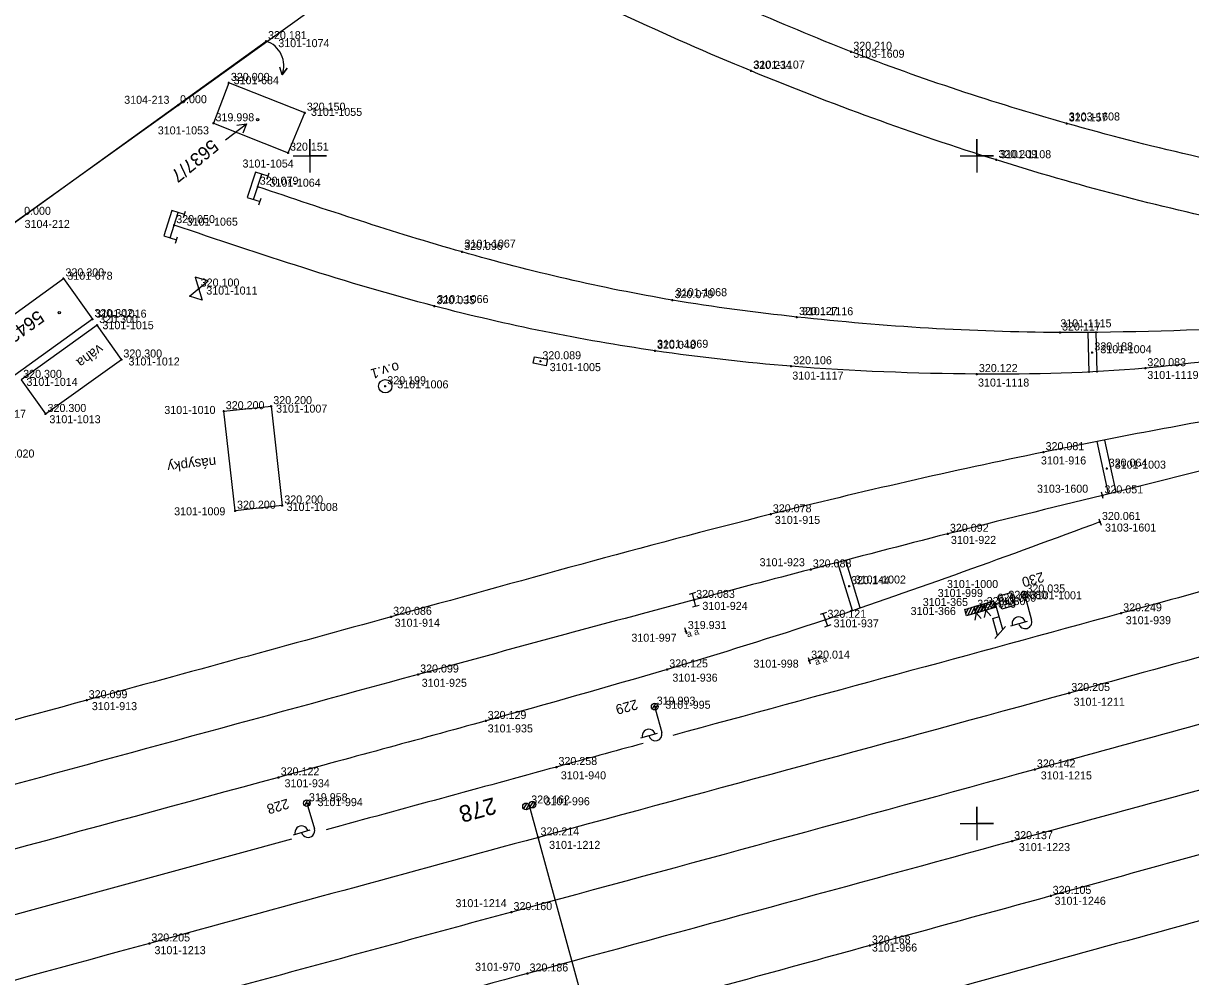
# Model space of a CAD drawing. Extents: x -821875 to -821475, y -1070280 to -1069975.
# Drawn here: x -821621.5 to -821534, y -1070161.5 to -1070090.1 of the extents above; entities that cross this region are included whole.
import ezdxf

# ---------------------------------------------------------------- set-up
doc = ezdxf.new("R2010")
doc.units = 0
for name, color, linetype in [('Vrstva 1', 7, 'Continuous'), ('Vrstva 10', 7, 'Continuous'), ('Vrstva 11', 7, 'Continuous'), ('Vrstva 15', 7, 'Continuous'), ('Vrstva 17', 7, 'Continuous'), ('Vrstva 2', 7, 'Continuous'), ('Vrstva 20', 7, 'Continuous'), ('Vrstva 21', 7, 'Continuous'), ('Vrstva 23', 7, 'Continuous'), ('Vrstva 25', 7, 'Continuous'), ('Vrstva 28', 7, 'Continuous'), ('Vrstva 3', 7, 'Continuous'), ('Vrstva 33', 7, 'Continuous'), ('Vrstva 36', 7, 'Continuous'), ('Vrstva 52', 7, 'Continuous'), ('Vrstva 53', 7, 'Continuous'), ('Vrstva 54', 7, 'Continuous'), ('Vrstva 57', 7, 'Continuous'), ('Vrstva 59', 7, 'Continuous'), ('Vrstva 6', 7, 'Continuous'), ('Vrstva 60', 7, 'Continuous'), ('Vrstva 61', 7, 'Continuous'), ('Vrstva 7', 7, 'Continuous')]:
    doc.layers.add(name, color=color, linetype=linetype)

# ---------------------------------------------------------------- blocks, each defined once
blk = doc.blocks.new('BOD')
at = {"layer": 'Vrstva 3'}
for p, q in [((-0.15, 0), (0.15, 0)), ((0, -0.15), (0, 0.15))]:
    blk.add_line(p, q, dxfattribs=at)

msp = doc.modelspace()

# ---------------------------------------------------------------- linework, layer by layer
at = {"layer": 'Vrstva 1'}
msp.add_line((-821601.389, -1070151.191), (-821624.154, -1070157.393), dxfattribs=at)
for points in [[(-821601.25, -1070100), (-821600, -1070100), (-821600, -1070098.75), (-821600, -1070100), (-821598.75, -1070100), (-821600, -1070100), (-821600, -1070101.25)], [(-821551.25, -1070100), (-821550, -1070100), (-821550, -1070098.75), (-821550, -1070100), (-821548.75, -1070100), (-821550, -1070100), (-821550, -1070101.25)], [(-821551.25, -1070150), (-821550, -1070150), (-821550, -1070148.75), (-821550, -1070150), (-821548.75, -1070150), (-821550, -1070150), (-821550, -1070151.25)]]:
    msp.add_lwpolyline(points, dxfattribs=at)
for points in [[(-821500, -1070107.532), (-821514.414, -1070107.377), (-821530.282, -1070105.08), (-821548.548, -1070100.3), (-821566.929, -1070093.631), (-821576.512, -1070089.417), (-821586.373, -1070084.578)], [(-821500, -1070104.505), (-821504.552, -1070104.218), (-821524.6, -1070101.851), (-821543.27, -1070097.565), (-821559.418, -1070092.193), (-821575.427, -1070085.277)], [(-821528.616, -1070112.837), (-821543.775, -1070113.227), (-821563.491, -1070112.067), (-821572.815, -1070110.801), (-821588.592, -1070107.193), (-821603.911, -1070102.306)], [(-821528.316, -1070114.765), (-821537.381, -1070115.9), (-821550.005, -1070116.34), (-821563.928, -1070115.755), (-821574.13, -1070114.598), (-821590.666, -1070111.251), (-821610.167, -1070105.183)], [(-821515.135, -1070116.801), (-821528.933, -1070119.148), (-821545.007, -1070122.191), (-821565.452, -1070126.847), (-821593.911, -1070134.524), (-821616.729, -1070140.773), (-821646.681, -1070148.977), (-821681.98, -1070158.691), (-821694.065, -1070162.076), (-821706.535, -1070165.88), (-821718.507, -1070169.937)], [(-821500, -1070124.347), (-821519.547, -1070129.021), (-821539.192, -1070134.264), (-821572.805, -1070143.407)], [(-821540.596, -1070125.428), (-821552.18, -1070128.307), (-821562.458, -1070130.974), (-821571.2, -1070133.262), (-821591.887, -1070138.848), (-821628.102, -1070148.713), (-821679.285, -1070162.663)], [(-821540.784, -1070127.42), (-821561.358, -1070134.748), (-821573.215, -1070138.464), (-821586.824, -1070142.326), (-821602.341, -1070146.553), (-821645.37, -1070158.257), (-821677.113, -1070166.912)], [(-821500, -1070129.211), (-821517.764, -1070133.43), (-821543.081, -1070140.233), (-821582.867, -1070151.05), (-821612.032, -1070158.997), (-821647.71, -1070168.745)], [(-821500, -1070134.157), (-821525.227, -1070140.424), (-821545.665, -1070145.962), (-821584.89, -1070156.649), (-821608.863, -1070163.173), (-821645.742, -1070173.228), (-821684.141, -1070183.689)], [(-821500, -1070139.002), (-821505.719, -1070140.359), (-821526.796, -1070145.75), (-821547.362, -1070151.333), (-821583.687, -1070161.245), (-821611.332, -1070168.765), (-821648.899, -1070179.006), (-821680.4, -1070187.609), (-821711.133, -1070195.974)], [(-821500, -1070143.947), (-821500.602, -1070144.082), (-821526.98, -1070150.62), (-821544.477, -1070155.432), (-821558.026, -1070159.151), (-821579.135, -1070164.951), (-821610.376, -1070173.463), (-821647.463, -1070183.595), (-821678.921, -1070192.191), (-821710.276, -1070200.761)], [(-821575.018, -1070144.009), (-821581.518, -1070145.779), (-821598.768, -1070150.477)], [(-821500, -1070148.817), (-821511.77, -1070151.622), (-821530.609, -1070156.564), (-821556.604, -1070163.701), (-821576.895, -1070169.217), (-821607.294, -1070177.525), (-821643.435, -1070187.343), (-821669.656, -1070194.488)], [(-821500, -1070158.612), (-821502.104, -1070159.113), (-821527.988, -1070165.772), (-821558.427, -1070174.094), (-821579.522, -1070179.891)]]:
    msp.add_spline(points, degree=3, dxfattribs=at)
at = {"layer": 'Vrstva 10'}
for p, q in [((-821548.369, -1070133.48), (-821548.849, -1070133.616)), ((-821548.065, -1070135.472), (-821548.609, -1070133.548)), ((-821547.865, -1070135.26), (-821548.65, -1070136.158))]:
    msp.add_line(p, q, dxfattribs=at)
msp.add_lwpolyline([(-821548.458, -1070135.921), (-821548.818, -1070134.646), (-821548.337, -1070134.51)], dxfattribs=at)
at = {"layer": 'Vrstva 11'}
for p, q in [((-821583.752, -1070148.483), (-821583.987, -1070148.894)), ((-821583.595, -1070148.587), (-821583.818, -1070148.976)), ((-821583.56, -1070148.661), (-821575.906, -1070176.676)), ((-821583.267, -1070148.352), (-821583.503, -1070148.764)), ((-821583.111, -1070148.457), (-821583.333, -1070148.845))]:
    msp.add_line(p, q, dxfattribs=at)
for centre in [(-821583.801, -1070148.727), (-821583.801, -1070148.727), (-821583.319, -1070148.595), (-821583.319, -1070148.595)]:
    msp.add_circle(centre, 0.25, dxfattribs=at)
at = {"layer": 'Vrstva 15'}
for p, q in [((-821604.215, -1070103.258), (-821603.607, -1070101.354)), ((-821603.207, -1070101.744), (-821603.055, -1070101.267)), ((-821603.815, -1070103.649), (-821603.663, -1070103.172)), ((-821610.464, -1070106.138), (-821609.87, -1070104.228)), ((-821609.466, -1070104.615), (-821609.318, -1070104.138)), ((-821610.061, -1070106.525), (-821609.912, -1070106.048))]:
    msp.add_line(p, q, dxfattribs=at)
for points in [[(-821603.131, -1070101.506), (-821604.083, -1070101.202), (-821604.691, -1070103.106), (-821603.739, -1070103.41)], [(-821609.392, -1070104.376), (-821610.348, -1070104.079), (-821610.942, -1070105.99), (-821609.986, -1070106.287)]]:
    msp.add_lwpolyline(points, dxfattribs=at)
at = {"layer": 'Vrstva 17'}
msp.add_lwpolyline([(-821638.053, -1070116.453), (-821603.288, -1070091.399)], dxfattribs=at)
at = {"layer": 'Vrstva 2'}
for p, q in [((-821540.536, -1070125.67), (-821540.656, -1070125.186)), ((-821540.873, -1070127.187), (-821540.695, -1070127.653))]:
    msp.add_line(p, q, dxfattribs=at)
msp.add_lwpolyline([(-821517.318, -1070119.351), (-821530.222, -1070122.85), (-821540.596, -1070125.428)], dxfattribs=at)
at = {"layer": 'Vrstva 20'}
msp.add_lwpolyline([(-821621.64, -1070116.774), (-821619.812, -1070119.329), (-821614.129, -1070115.247), (-821615.939, -1070112.668), (-821621.64, -1070116.774)], dxfattribs=at)
at = {"layer": 'Vrstva 21'}
msp.add_lwpolyline([(-821607.633, -1070109.365), (-821608.589, -1070109.068), (-821608.079, -1070110.798), (-821609.035, -1070110.501), (-821607.633, -1070109.365)], dxfattribs=at)
at = {"layer": 'Vrstva 23'}
for p, q in [((-821602.089, -1070093.922), (-821602.258, -1070093.336)), ((-821601.706, -1070093.419), (-821602.089, -1070093.922)), ((-821602.089, -1070093.922), (-821601.706, -1070093.419))]:
    msp.add_line(p, q, dxfattribs=at)
for points in [[(-821606.072, -1070094.526), (-821607.224, -1070097.55), (-821601.639, -1070099.754), (-821600.383, -1070096.757), (-821606.072, -1070094.526)], [(-821627.52, -1070115.73), (-821618.47, -1070109.17), (-821616.3, -1070112.22), (-821625.37, -1070118.75), (-821627.52, -1070115.73)], [(-821606.456, -1070119.122), (-821602.893, -1070118.744), (-821602.068, -1070126.181), (-821605.612, -1070126.576), (-821606.456, -1070119.122)]]:
    msp.add_lwpolyline(points, dxfattribs=at)
msp.add_arc((-821603.875, -1070093.224), 1.917, 338.65588, 72.17576, dxfattribs=at)
at = {"layer": 'Vrstva 25'}
for p, q in [((-821546.385, -1070132.608), (-821546.619, -1070133.024)), ((-821546.231, -1070132.716), (-821546.446, -1070133.098)), ((-821546.374, -1070133.091), (-821545.903, -1070134.776)), ((-821546.24, -1070134.87), (-821547.491, -1070135.22)), ((-821574.097, -1070141.013), (-821574.335, -1070141.429)), ((-821573.943, -1070141.122), (-821574.162, -1070141.504)), ((-821574.089, -1070141.496), (-821573.629, -1070143.185)), ((-821573.967, -1070143.277), (-821575.222, -1070143.619)), ((-821600.17, -1070148.249), (-821600.399, -1070148.668)), ((-821600.014, -1070148.355), (-821600.225, -1070148.74)), ((-821600.153, -1070148.732), (-821599.662, -1070150.411)), ((-821599.997, -1070150.51), (-821601.245, -1070150.875))]:
    msp.add_line(p, q, dxfattribs=at)
msp.add_lwpolyline([(-821582.187, -1070115.227), (-821582.28, -1070115.719), (-821583.263, -1070115.535), (-821583.17, -1070115.043), (-821582.187, -1070115.227)], dxfattribs=at)
for centre, radius in [((-821594.348, -1070117.251), 0.5), ((-821546.441, -1070132.85), 0.25), ((-821546.441, -1070132.85), 0.25), ((-821574.155, -1070141.255), 0.25), ((-821574.155, -1070141.255), 0.25), ((-821600.223, -1070148.492), 0.25), ((-821600.223, -1070148.492), 0.25)]:
    msp.add_circle(centre, radius, dxfattribs=at)
for centre, start, end in [((-821546.867, -1070135.039), 14.91738, 196.32252), ((-821546.384, -1070134.911), 195.61995, 15.61995), ((-821574.596, -1070143.442), 14.53457, 195.93972), ((-821574.112, -1070143.316), 195.23715, 15.23715), ((-821600.623, -1070150.686), 15.60804, 197.01318), ((-821600.141, -1070150.552), 196.31061, 16.31061)]:
    msp.add_arc(centre, 0.5, start, end, dxfattribs=at)
at = {"layer": 'Vrstva 28'}
for p, q in [((-821550.124, -1070133.737), (-821550.464, -1070134.356)), ((-821549.869, -1070133.663), (-821550.209, -1070134.282)), ((-821550.173, -1070133.751), (-821550.197, -1070133.794)), ((-821549.918, -1070133.679), (-821550.124, -1070134.049)), ((-821549.663, -1070133.606), (-821550.007, -1070134.223)), ((-821549.615, -1070133.588), (-821549.955, -1070134.208)), ((-821549.409, -1070133.533), (-821549.751, -1070134.15)), ((-821549.446, -1070133.67), (-821549.7, -1070134.134)), ((-821549.154, -1070133.46), (-821549.497, -1070134.078)), ((-821548.899, -1070133.387), (-821549.242, -1070134.005)), ((-821548.73, -1070133.47), (-821548.987, -1070133.932)), ((-821548.657, -1070133.725), (-821548.732, -1070133.859)), ((-821550.887, -1070133.959), (-821550.911, -1070134.002)), ((-821550.633, -1070133.885), (-821550.837, -1070134.257)), ((-821550.378, -1070133.811), (-821550.718, -1070134.43)), ((-821549.372, -1070133.925), (-821549.446, -1070134.059))]:
    msp.add_line(p, q, dxfattribs=at)
for points in [[(-821549.341, -1070134.029), (-821550.781, -1070134.449), (-821550.921, -1070133.969), (-821549.481, -1070133.549)], [(-821548.627, -1070133.829), (-821550.069, -1070134.241), (-821550.207, -1070133.761), (-821548.765, -1070133.349)]]:
    msp.add_lwpolyline(points, close=True, dxfattribs=at)
for points in [[(-821549.341, -1070134.029), (-821550.781, -1070134.449), (-821550.921, -1070133.969), (-821549.481, -1070133.549), (-821549.341, -1070134.029)], [(-821548.627, -1070133.829), (-821550.069, -1070134.241), (-821550.207, -1070133.761), (-821548.765, -1070133.349), (-821548.627, -1070133.829)], [(-821549.681, -1070134.649), (-821550.061, -1070134.239), (-821550.161, -1070134.789)], [(-821548.971, -1070134.447), (-821549.349, -1070134.035), (-821549.451, -1070134.585)]]:
    msp.add_lwpolyline(points, dxfattribs=at)
at = {"layer": 'Vrstva 3'}
for p, q in [((-821571.087, -1070132.715), (-821571.57, -1070132.843)), ((-821571.072, -1070133.745), (-821571.328, -1070132.779)), ((-821570.83, -1070133.681), (-821571.313, -1070133.809)), ((-821561.29, -1070134.193), (-821561.762, -1070134.361)), ((-821561.19, -1070135.219), (-821561.526, -1070134.277)), ((-821560.954, -1070135.135), (-821561.426, -1070135.303))]:
    msp.add_line(p, q, dxfattribs=at)
at = {"layer": 'Vrstva 33'}
for p, q in [((-821547.489, -1070133.498), (-821547.971, -1070133.634)), ((-821547.73, -1070133.566), (-821547.866, -1070133.084))]:
    msp.add_line(p, q, dxfattribs=at)
msp.add_lwpolyline([(-821547.181, -1070133.671), (-821548.144, -1070133.942), (-821548.415, -1070132.979), (-821547.452, -1070132.708), (-821547.181, -1070133.671)], dxfattribs=at)
at = {"layer": 'Vrstva 52'}
for points in [[(-821607.224, -1070097.55), (-821601.639, -1070099.754), (-821600.383, -1070096.757), (-821606.072, -1070094.526), (-821607.224, -1070097.55)], [(-821627.52, -1070115.73), (-821618.47, -1070109.17), (-821616.3, -1070112.22), (-821625.37, -1070118.75), (-821627.52, -1070115.73)]]:
    msp.add_lwpolyline(points, dxfattribs=at)
at = {"layer": 'Vrstva 53'}
msp.add_lwpolyline([(-821734.56, -1070151.86), (-821659.89, -1070131.96), (-821621.57, -1070104.56), (-821609.88, -1070096.2), (-821593.26, -1070084.26), (-821583.18, -1070077.05), (-821575.55, -1070071.56), (-821563.91, -1070063.18), (-821553.98, -1070056.16), (-821553.05, -1070055.49), (-821551.21, -1070054.16)], dxfattribs=at)
at = {"layer": 'Vrstva 54'}
msp.add_line((-821605.488, -1070097.685), (-821604.743, -1070097.59), dxfattribs=at)
msp.add_lwpolyline([(-821606.336, -1070098.8), (-821604.743, -1070097.59), (-821605.034, -1070098.282)], dxfattribs=at)
at = {"layer": 'Vrstva 59'}
for centre in [(-821603.917, -1070097.29), (-821618.789, -1070111.748)]:
    msp.add_circle(centre, 0.0873, dxfattribs=at)
at = {"layer": 'Vrstva 6'}
for p, q in [((-821571.758, -1070135.831), (-821571.888, -1070135.347)), ((-821562.657, -1070137.569), (-821562.499, -1070138.043)), ((-821561.64, -1070137.49), (-821562.578, -1070137.806))]:
    msp.add_line(p, q, dxfattribs=at)
at = {"layer": 'Vrstva 7'}
for p, q in [((-821541.701, -1070113.174), (-821541.608, -1070116.256)), ((-821541.102, -1070113.158), (-821541.009, -1070116.224)), ((-821541.026, -1070121.4), (-821540.169, -1070125.322)), ((-821540.437, -1070121.285), (-821539.586, -1070125.177)), ((-821559.864, -1070130.294), (-821558.778, -1070133.829)), ((-821560.444, -1070130.446), (-821559.343, -1070134.03))]:
    msp.add_line(p, q, dxfattribs=at)

# ---------------------------------------------------------------- block references
at = {"layer": 'Vrstva 60', "xscale": 0.5, "yscale": 0.5}
for p in [(-821603.288, -1070091.399), (-821559.418, -1070092.193), (-821566.929, -1070093.631), (-821606.072, -1070094.526), (-821609.88, -1070096.2), (-821600.383, -1070096.757), (-821607.224, -1070097.55), (-821543.27, -1070097.565), (-821601.639, -1070099.754), (-821548.548, -1070100.3), (-821603.911, -1070102.306), (-821610.167, -1070105.183), (-821588.592, -1070107.193), (-821618.47, -1070109.17), (-821608.334, -1070109.933), (-821572.815, -1070110.801), (-821590.666, -1070111.251), (-821616.3, -1070112.22), (-821615.939, -1070112.668), (-821563.491, -1070112.067), (-821543.775, -1070113.227), (-821574.13, -1070114.598), (-821614.129, -1070115.247), (-821582.725, -1070115.381), (-821541.355, -1070114.715), (-821563.928, -1070115.755), (-821550.005, -1070116.34), (-821537.381, -1070115.9), (-821594.348, -1070117.251), (-821602.893, -1070118.744), (-821619.812, -1070119.329), (-821606.456, -1070119.122), (-821545.007, -1070122.191), (-821540.276, -1070123.425), (-821540.596, -1070125.428), (-821605.612, -1070126.576), (-821602.068, -1070126.181), (-821565.452, -1070126.847), (-821540.784, -1070127.42), (-821552.18, -1070128.307), (-821562.458, -1070130.974), (-821559.582, -1070132.232), (-821546.441, -1070132.85), (-821571.2, -1070133.262), (-821549.417, -1070133.795), (-821548.609, -1070133.548), (-821547.798, -1070133.325), (-821593.911, -1070134.524), (-821561.358, -1070134.748), (-821550.131, -1070133.999), (-821539.192, -1070134.264), (-821571.823, -1070135.589), (-821562.578, -1070137.806), (-821591.887, -1070138.848), (-821573.215, -1070138.464), (-821616.729, -1070140.773), (-821543.081, -1070140.233), (-821574.155, -1070141.255), (-821586.824, -1070142.326), (-821581.518, -1070145.779), (-821545.665, -1070145.962), (-821602.341, -1070146.553), (-821600.223, -1070148.492), (-821583.56, -1070148.661), (-821582.867, -1070151.05), (-821547.362, -1070151.333), (-821544.477, -1070155.432), (-821584.89, -1070156.649), (-821612.032, -1070158.997), (-821558.026, -1070159.151), (-821583.687, -1070161.245)]:
    msp.add_blockref('BOD', p, dxfattribs=at)

# ---------------------------------------------------------------- texts
at = {"layer": 'Vrstva 11'}
msp.add_text('278', height=1.25, rotation=195.23495, dxfattribs=at).set_placement((-821586.235, -1070148.029))
at = {"layer": 'Vrstva 20'}
msp.add_text('váha', height=0.75, rotation=215.76236, dxfattribs=at).set_placement((-821615.804, -1070114.052))
at = {"layer": 'Vrstva 25'}
for s, rotation, p in [('o.v.1', 195.25346, (-821593.41, -1070115.427)), ('230', 195.61996, (-821545.093, -1070131.158)), ('229', 195.23715, (-821575.538, -1070140.706)), ('228', 196.31067, (-821601.692, -1070148.142))]:
    msp.add_text(s, height=0.75, rotation=rotation, dxfattribs=at).set_placement(p)
at = {"layer": 'Vrstva 36'}
msp.add_text('násypky', height=0.75, rotation=186.35971, dxfattribs=at).set_placement((-821607.061, -1070122.544))
at = {"layer": 'Vrstva 57'}
for s, rotation, p in [('5637/7', 219.43183, (-821607.37, -1070098.69)), ('5643', 215.69159, (-821620.383, -1070111.511))]:
    msp.add_text(s, height=1, rotation=rotation, dxfattribs=at).set_placement(p)
at = {"layer": 'Vrstva 6'}
for s, rotation, p in [('a a', 14.91827, (-821571.694, -1070136.071)), ('  a a', 18.61162, (-821562.418, -1070138.28))]:
    msp.add_text(s, height=0.5, rotation=rotation, dxfattribs=at).set_placement(p)
at = {"layer": 'Vrstva 60'}
for s, p in [('3101-1074', (-821602.37, -1070091.849)), ('3103-1609', (-821559.268, -1070092.643)), ('3101-1107', (-821566.744, -1070093.453)), ('3101-684', (-821605.713, -1070094.628)), ('3104-213', (-821613.918, -1070096.092)), ('3101-1055', (-821599.919, -1070096.998)), ('3103-1608', (-821543.12, -1070097.343)), ('3101-1053', (-821611.401, -1070098.383)), ('3101-1108', (-821548.275, -1070100.169)), ('3101-1054', (-821605.049, -1070100.867)), ('3101-1064', (-821603.028, -1070102.303)), ('3104-212', (-821621.385, -1070105.393)), ('3101-1065', (-821609.237, -1070105.222)), ('3101-1067', (-821588.409, -1070106.867)), ('3101-678', (-821618.18, -1070109.272)), ('3101-1011', (-821607.765, -1070110.383)), ('3101-1068', (-821572.568, -1070110.507)), ('3101-1066', (-821590.451, -1070111.022)), ('3101-1016', (-821616.08, -1070112.112)), ('3101-1116', (-821563.114, -1070111.935)), ('3101-1015', (-821615.544, -1070112.979)), ('3101-1115', (-821543.754, -1070112.837)), ('3101-1069', (-821573.98, -1070114.369)), ('3101-1004', (-821540.751, -1070114.778)), ('3101-1012', (-821613.595, -1070115.697)), ('3101-1005', (-821582.025, -1070116.122)), ('3101-1117', (-821563.843, -1070116.754)), ('3101-1119', (-821537.231, -1070116.706)), ('3101-1014', (-821621.245, -1070117.224)), ('3101-1006', (-821593.453, -1070117.41)), ('3101-1118', (-821549.92, -1070117.274)), ('3101-1010', (-821610.913, -1070119.328)), ('3101-1007', (-821602.534, -1070119.229)), ('3101-1017', (-821625.116, -1070119.618)), ('3101-1013', (-821619.522, -1070120.023)), ('3101-1020', (-821624.483, -1070122.593)), ('3101-916', (-821545.207, -1070123.111)), ('3101-1003', (-821539.673, -1070123.423)), ('3103-1600', (-821545.502, -1070125.228)), ('3101-1009', (-821610.174, -1070126.921)), ('3101-1008', (-821601.744, -1070126.596)), ('3101-915', (-821565.149, -1070127.565)), ('3103-1601', (-821540.404, -1070128.138)), ('3101-922', (-821551.954, -1070129.064)), ('3101-923', (-821566.292, -1070130.735)), ('3101-1002', (-821559.164, -1070132.032)), ('3101-1000', (-821552.251, -1070132.367)), ('3101-999', (-821552.944, -1070133.04)), ('3101-1001', (-821545.972, -1070133.211)), ('3101-924', (-821570.58, -1070134.005)), ('3101-366', (-821554.975, -1070134.39)), ('3101-365', (-821554.065, -1070133.716)), ('3101-914', (-821593.643, -1070135.268)), ('3101-939', (-821538.849, -1070135.079)), ('3101-937', (-821560.748, -1070135.313)), ('3101-997', (-821575.903, -1070136.391)), ('3101-998', (-821566.756, -1070138.332)), ('3101-936', (-821572.83, -1070139.384)), ('3101-925', (-821591.619, -1070139.768)), ('3101-995', (-821573.359, -1070141.412)), ('3101-1211', (-821542.757, -1070141.186)), ('3101-913', (-821616.344, -1070141.517)), ('3101-935', (-821586.674, -1070143.187)), ('3101-934', (-821601.898, -1070147.296)), ('3101-940', (-821581.192, -1070146.699)), ('3101-1215', (-821545.221, -1070146.706)), ('3101-994', (-821599.427, -1070148.707)), ('3101-996', (-821582.411, -1070148.642)), ('3101-1212', (-821582.07, -1070151.911)), ('3101-1223', (-821546.86, -1070152.077)), ('3101-1214', (-821589.088, -1070156.277)), ('3101-1246', (-821544.183, -1070156.098)), ('3101-966', (-821557.876, -1070159.601)), ('3101-1213', (-821611.647, -1070159.799)), ('3101-970', (-821587.619, -1070161.045))]:
    msp.add_text(s, height=0.6, dxfattribs=at).set_placement(p)
at = {"layer": 'Vrstva 61'}
for s, p in [('320.181', (-821603.138, -1070091.249)), ('320.210', (-821559.268, -1070092.043)), ('320.234', (-821566.779, -1070093.481)), ('320.000', (-821605.922, -1070094.376)), ('0.000', (-821609.73, -1070096.05)), ('320.150', (-821600.233, -1070096.607)), ('319.998', (-821607.074, -1070097.4)), ('320.157', (-821543.12, -1070097.415)), ('320.151', (-821601.489, -1070099.604)), ('320.209', (-821548.398, -1070100.15)), ('320.079', (-821603.761, -1070102.156)), ('0.000', (-821621.42, -1070104.41)), ('320.050', (-821610.017, -1070105.033)), ('320.096', (-821588.442, -1070107.043)), ('320.300', (-821618.32, -1070109.02)), ('320.100', (-821608.184, -1070109.783)), ('320.079', (-821572.665, -1070110.651)), ('320.035', (-821590.516, -1070111.101)), ('320.302', (-821616.15, -1070112.07)), ('320.300', (-821615.789, -1070112.518)), ('320.127', (-821563.341, -1070111.917)), ('320.117', (-821543.625, -1070113.077)), ('320.300', (-821613.979, -1070115.097)), ('320.048', (-821573.98, -1070114.448)), ('320.188', (-821541.205, -1070114.565)), ('320.089', (-821582.575, -1070115.231)), ('320.106', (-821563.778, -1070115.605)), ('320.083', (-821537.231, -1070115.75)), ('320.300', (-821621.49, -1070116.624)), ('320.122', (-821549.855, -1070116.19)), ('320.199', (-821594.198, -1070117.101)), ('320.200', (-821602.743, -1070118.594)), ('320.300', (-821619.662, -1070119.179)), ('320.200', (-821606.306, -1070118.972)), ('320.081', (-821544.857, -1070122.041)), ('320.064', (-821540.126, -1070123.275)), ('320.051', (-821540.446, -1070125.278)), ('320.200', (-821605.462, -1070126.426)), ('320.200', (-821601.918, -1070126.031)), ('320.078', (-821565.302, -1070126.697)), ('320.061', (-821540.634, -1070127.27)), ('320.092', (-821552.03, -1070128.157)), ('320.088', (-821562.308, -1070130.824)), ('320.144', (-821559.432, -1070132.082)), ('320.083', (-821571.05, -1070133.112)), ('320.080', (-821548.459, -1070133.398)), ('320.080', (-821547.648, -1070133.175)), ('320.035', (-821546.291, -1070132.7)), ('320.086', (-821593.761, -1070134.374)), ('320.080', (-821549.981, -1070133.849)), ('320.080', (-821549.267, -1070133.645)), ('320.249', (-821539.042, -1070134.114)), ('320.121', (-821561.208, -1070134.598)), ('319.931', (-821571.673, -1070135.439)), ('320.014', (-821562.428, -1070137.656)), ('320.099', (-821591.737, -1070138.698)), ('320.125', (-821573.065, -1070138.314)), ('320.205', (-821542.931, -1070140.083)), ('320.099', (-821616.579, -1070140.623)), ('319.993', (-821574.005, -1070141.105)), ('320.129', (-821586.674, -1070142.176)), ('320.258', (-821581.368, -1070145.629)), ('320.122', (-821602.191, -1070146.403)), ('320.142', (-821545.515, -1070145.812)), ('319.958', (-821600.073, -1070148.342)), ('320.162', (-821583.41, -1070148.511)), ('320.214', (-821582.717, -1070150.9)), ('320.137', (-821547.212, -1070151.183)), ('320.105', (-821544.327, -1070155.282)), ('320.160', (-821584.74, -1070156.499)), ('320.205', (-821611.882, -1070158.847)), ('320.168', (-821557.876, -1070159.001)), ('320.186', (-821583.537, -1070161.095))]:
    msp.add_text(s, height=0.6, dxfattribs=at).set_placement(p)

doc.saveas('drawing.dxf')
